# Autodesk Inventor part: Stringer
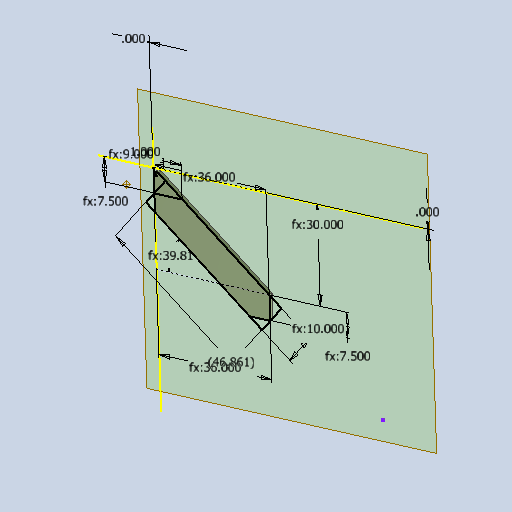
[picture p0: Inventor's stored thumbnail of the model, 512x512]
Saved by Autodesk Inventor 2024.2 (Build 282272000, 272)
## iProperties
Created: 2022-06
Part Number: Stringer
Material: Steel, Galvanized
Document SubType Name: Modeling
Designer: reaumed
Density: 7.85 g/cm^3
Appearance: Galvanized
Mass: 28099.6 g
Surface Area: 11501.7 cm^2
Volume: 3579.57 cm^3
Author: reaumed
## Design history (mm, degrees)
node "Half the Width Workplane"
sketch "Stringer Profile Sketch"
  geometry: L1 (0, 0)-(-914.4, 0); L2 (-914.4, 0)-(-914.4, -762); L3 (-914.4, -762)-(0, -762); L4 (0, -762)-(0, 0); L5 (-845.482, -1035.202)-(68.918, -273.202); L6 (68.918, -273.202)-(-93.689, -78.074); L7 (-93.689, -78.074)-(-1008.089, -840.074); L8 (-1008.089, -840.074)-(-845.482, -1035.202); L9 (0, -190.5)-(-228.6, -190.5); L10 (0, -190.5)-(0, -330.634); L11 (-746.239, -952.5)-(-914.4, -952.5); L12 (-914.4, -952.5)-(-914.4, -762); L13 (0, -1812.658)-(0, 302.11) reference; L14 (-2188.973, 0)-(445.234, 0) reference; L15 (0, -190.5)-(0, -54.23); L16 (-93.689, -78.074)-(-41.661, -34.717); A1 r 25.4 centre (-25.4, -54.23) between (0, -54.23) and (-41.661, -34.717); 8 further points
  constraints: 28 end point, 9 point on line, 4 parallel, 3 horizontal, 2 collinear, 2 perpendicular, 2 point on circle, 2 tangent, 2 vertical, 1 centre point
  dimensions: "d152" = 762 distance of L1.end L2.end (derived); "d153" = 914.4 distance of L2.end L3.end (derived); "d155" = 254 distance of L7.end L5.start (derived); "d156" = 1190.28205 distance of L6.end L7.end (derived); "d157" = 39.8056 deg angle of L3 L5 (derived); "d158" = 228.6 distance of L9.start L9.end (derived); "d159" = 190.5 distance of L11.end L12.end (derived); "d160" = 190.5 distance between parallel lines of L1 L9 (derived); "d161" = 914.4 distance between parallel lines of L12 L10 (derived); "d162" = 0 distance between parallel lines of L4 L13; "d163" = 0 distance between parallel lines of L1 L14; "d190" = 25.4 radius of A1 (derived)
extrude "Stringer Extrusion" new body sketch "Stringer Profile Sketch" distance "d164" = 38.1 (derived); taper "d165" = 0 deg
shell "Shell1" dims "d189" = 6.35 (derived)
body "Solid2"
other parameters: "StringerSpacing" = 342.9 (derived), "StringerWallThickness" = 6.35 [user parameter]
